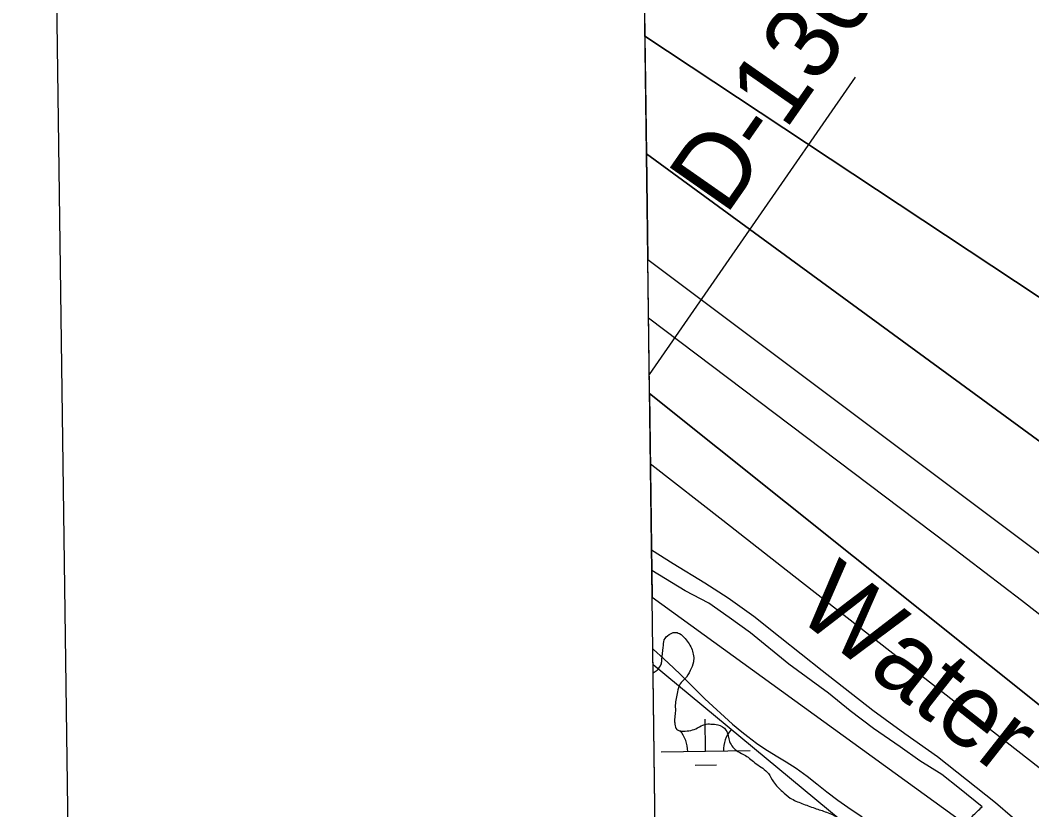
# Model space of a CAD drawing. Extents: x 3753511 to 3791668, y 379550 to 405377.
# Drawn here: x 3756853 to 3757989, y 399790 to 400676 of the extents above; entities that cross this region are included whole.
import ezdxf

# ---------------------------------------------------------------- set-up
doc = ezdxf.new("R2010")
doc.units = 0
for name, color, linetype in [('V-ANNO-SYMB', 7, 'Continuous'), ('V-GRID-FRAM', 7, 'Continuous'), ('V-RIVR-EDGE', 7, 'Continuous'), ('V-RIVR-IDEN', 7, 'Continuous'), ('V-RIVR-RANG', 7, 'Continuous'), ('V-RIVR-RANG-IDEN', 7, 'Continuous'), ('V-RRAP-FSHR', 7, 'Continuous'), ('V-TOPO-DPTH', 7, 'Continuous'), ('V-TOPO-MINR', 7, 'Continuous'), ('V-TOPO-WATR', 7, 'Continuous'), ('V-WETL-SWMP', 7, 'Continuous')]:
    doc.layers.add(name, color=color, linetype=linetype)

msp = doc.modelspace()

# ---------------------------------------------------------------- linework, layer by layer
at = {"layer": 'V-ANNO-SYMB'}
msp.add_lwpolyline([(3757162.5, 380795.6), (3790242.7, 381242.9), (3789932.8, 404157.4), (3756852.6, 403710.1), (3757162.5, 380795.6)], dxfattribs=at)
at = {"layer": 'V-GRID-FRAM'}
msp.add_lwpolyline([(3757521.7, 403151.1), (3789298.9, 403581), (3789552.8, 385400.3), (3757759.7, 384970.3), (3757521.7, 403151.1)], dxfattribs=at)
at = {"layer": 'V-RIVR-EDGE'}
for p, q in [((3757561.9, 400081.8), (3757586.1, 400066.5)), ((3757586.1, 400066.5), (3757621.6, 400044.9)), ((3757599.7, 400035.7), (3757562.2, 400058.7)), ((3757621.6, 400044.9), (3757647.8, 400027.9)), ((3757626, 400021.9), (3757599.7, 400035.7)), ((3757649, 400006.1), (3757626, 400021.9)), ((3757647.8, 400027.9), (3757676.5, 400007.6)), ((3757672.8, 399988.6), (3757649, 400006.1)), ((3757676.5, 400007.6), (3757706.4, 399983.7)), ((3757716, 399953.7), (3757672.8, 399988.6)), ((3757706.4, 399983.7), (3757753.6, 399946.4)), ((3757760.4, 399920.9), (3757716, 399953.7)), ((3757753.6, 399946.4), (3757810.5, 399902.1)), ((3757785, 399901), (3757760.4, 399920.9)), ((3757811.2, 399881.5), (3757785, 399901)), ((3757810.5, 399902.1), (3757824.2, 399892)), ((3757824.2, 399892), (3757846.4, 399875.8)), ((3757841.1, 399860.8), (3757811.2, 399881.5)), ((3757846.4, 399875.8), (3757883.1, 399849.8)), ((3757863.3, 399845), (3757841.1, 399860.8)), ((3757887.9, 399829.6), (3757863.3, 399845)), ((3757883.1, 399849.8), (3757948.1, 399798.3)), ((3757907.7, 399814.2), (3757887.9, 399829.6)), ((3757933.1, 399793.5), (3757907.7, 399814.2)), ((3757948.1, 399798.3), (3757986.4, 399765.4))]:
    msp.add_line(p, q, dxfattribs=at)
msp.add_spline([(3757563.7, 399944), (3757565.9, 399945.2), (3757570, 399949.2), (3757572.8, 399954.1), (3757573.3, 399958.9), (3757574.9, 399972.3), (3757576.1, 399980.8), (3757581.4, 399986.8), (3757587.9, 399989.2), (3757593.1, 399988), (3757599.6, 399982.3), (3757607.3, 399969.8), (3757608.8, 399956), (3757605.2, 399946.3), (3757599.1, 399937), (3757593.8, 399931.4), (3757591, 399922.5), (3757588.5, 399907.5), (3757588.5, 399899.1), (3757587.6, 399891.8), (3757588, 399886.1), (3757590, 399880.4), (3757593.3, 399878.8), (3757597.7, 399878.4), (3757613.5, 399882), (3757621.6, 399886), (3757628.5, 399886.4), (3757636.2, 399885.6), (3757645.4, 399879.5), (3757649.5, 399866.6), (3757658.7, 399855.6), (3757667.2, 399851.1), (3757679.3, 399841.8), (3757693, 399830.9), (3757698.7, 399821.5), (3757708.8, 399810.6), (3757717.6, 399803.3), (3757730.6, 399797.2), (3757745.1, 399791.9), (3757758.4, 399787.4), (3757772.6, 399780.5), (3757779.4, 399774.8), (3757786.3, 399763.9), (3757787.5, 399754.6), (3757790.3, 399741.7), (3757797.5, 399727.5), (3757806.8, 399714.1), (3757811.6, 399710.1), (3757818.9, 399710), (3757825, 399710.4), (3757839.1, 399716.9), (3757842.4, 399724.5), (3757849.7, 399748.4), (3757858.3, 399761.3), (3757870.4, 399768.6), (3757880.5, 399770.1), (3757899.5, 399770.5), (3757905.6, 399771.7), (3757922.2, 399783), (3757933.1, 399793.5)], degree=3, dxfattribs=at)
at = {"layer": 'V-RIVR-RANG'}
msp.add_line((3757559.3, 400278.6), (3757790.9, 400612.5), dxfattribs=at)
at = {"layer": 'V-RRAP-FSHR'}
msp.add_lwpolyline([(3757563.6, 399953.3), (3758068.9, 399534.7), (3758900.8, 398913.1), (3760489.6, 397842.2), (3761272.5, 397284.7), (3762001.9, 396825.7), (3763933.7, 395486.8), (3764514.9, 395076.7), (3765451.6, 394530.5), (3766076.4, 394191.3), (3766545.3, 393960.3), (3766679.9, 393930.1), (3766808.6, 393885.6), (3766901.8, 393826.8), (3766956.5, 393779.4), (3767086.7, 393701), (3767307.3, 393607.9), (3767495.3, 393505.5), (3767658.4, 393397.5), (3767773.5, 393285.8), (3767959.6, 393143.9), (3768482.9, 392725.4)], dxfattribs=at)
at = {"layer": 'V-TOPO-DPTH'}
for p, q in [((3757554.3, 400658.4), (3757556.1, 400526.3)), ((3757556.1, 400526.3), (3757557.6, 400407.9)), ((3757559.6, 400257.2), (3757557.6, 400407.9)), ((3757559.6, 400257.2), (3757562.6, 400028.8))]:
    msp.add_line(p, q, dxfattribs=at)
for points in [[(3757521.7, 403151.1), (3757554.3, 400658.4), (3758308.3, 400159.7), (3758311.3, 400157.8), (3758314.3, 400155.9), (3758317.4, 400154), (3758320.5, 400152.2), (3758446.1, 400079.5), (3758472.2, 400065.7), (3758498.8, 400053.3), (3758526.4, 400042.9), (3758554.5, 400033.8), (3758583.1, 400026.7), (3758612, 400020.7), (3758641.2, 400016.3), (3758670.6, 400013), (3758683.9, 400011.9), (3758719.7, 400007.4), (3758755.1, 400000.9), (3758789.8, 399991.4), (3758824, 399979.9), (3759244.8, 399818.4)], [(3759244.8, 399818.4), (3758824, 399979.9), (3758789.8, 399991.4), (3758755.1, 400000.9), (3758719.7, 400007.4), (3758683.9, 400011.9), (3758670.6, 400013), (3758641.2, 400016.3), (3758612, 400020.7), (3758583.1, 400026.7), (3758554.5, 400033.8), (3758526.4, 400042.9), (3758498.8, 400053.3), (3758472.2, 400065.7), (3758446.1, 400079.5), (3758320.5, 400152.2), (3758317.4, 400154), (3758314.3, 400155.9), (3758311.3, 400157.8), (3758308.3, 400159.7), (3757554.3, 400658.4)], [(3759035, 399447.3), (3759005.6, 399469.2), (3758976.2, 399491), (3758946.7, 399512.8), (3758917.2, 399534.5), (3758887.6, 399556.1), (3758858, 399577.7), (3758832.2, 399596.4), (3758789.6, 399627.3), (3758747, 399658.2), (3758704.4, 399689.1), (3758661.8, 399720), (3758543.7, 399805.6), (3758491.5, 399843.5), (3758439.4, 399881.3), (3758387.3, 399919.2), (3758335.2, 399957.1), (3758275.9, 400000.4), (3758253.5, 400016.7), (3758231.1, 400033.1), (3758208.8, 400049.4), (3758186.4, 400065.7), (3757556.1, 400526.3)], [(3757556.1, 400526.3), (3758186.4, 400065.7), (3758208.8, 400049.4), (3758231.1, 400033.1), (3758253.5, 400016.7), (3758275.9, 400000.4), (3758335.2, 399957.1), (3758387.3, 399919.2), (3758439.4, 399881.3), (3758491.5, 399843.5), (3758543.7, 399805.6), (3758661.8, 399720), (3758704.4, 399689.1), (3758747, 399658.2), (3758789.6, 399627.3), (3758832.2, 399596.4), (3758858, 399577.7), (3758887.6, 399556.1), (3758917.2, 399534.5), (3758946.7, 399512.8), (3758976.2, 399491), (3759005.6, 399469.2), (3759035, 399447.3)], [(3757557.6, 400407.9), (3758125.4, 399982.5), (3758149.2, 399964.7), (3758173, 399946.9), (3758196.8, 399929.2), (3758220.6, 399911.4), (3758267.2, 399876.8), (3758309.8, 399844.9), (3758352.2, 399812.8), (3758394.4, 399780.4)], [(3757557.6, 400407.9), (3758125.4, 399982.5), (3758149.2, 399964.7), (3758173, 399946.9), (3758196.8, 399929.2), (3758220.6, 399911.4), (3758267.2, 399876.8), (3758309.8, 399844.9), (3758352.2, 399812.8), (3758394.4, 399780.4)], [(3759483.3, 398745.3), (3758900.4, 399209), (3758704.3, 399361.8), (3758606.2, 399438.1), (3758507.9, 399514.1), (3758409.3, 399589.9), (3758310.6, 399665.4), (3758094.3, 399830.3), (3757559.6, 400257.2)], [(3759483.3, 398745.3), (3758900.4, 399209), (3758704.3, 399361.8), (3758606.2, 399438.1), (3758507.9, 399514.1), (3758409.3, 399589.9), (3758310.6, 399665.4), (3758094.3, 399830.3), (3757559.6, 400257.2)], [(3757562.6, 400028.8), (3757970, 399733.8)]]:
    msp.add_lwpolyline(points, dxfattribs=at)
at = {"layer": 'V-TOPO-MINR'}
for points in [[(3757554.3, 400658.4), (3758308.3, 400159.7), (3758311.3, 400157.8), (3758314.3, 400155.9), (3758317.4, 400154), (3758320.5, 400152.2), (3758446.1, 400079.5), (3758472.2, 400065.7), (3758498.8, 400053.3), (3758526.4, 400042.9), (3758554.5, 400033.8), (3758583.1, 400026.7), (3758612, 400020.7), (3758641.2, 400016.3), (3758670.6, 400013), (3758683.9, 400011.9), (3758719.7, 400007.4), (3758755.1, 400000.9), (3758789.8, 399991.4), (3758824, 399979.9), (3759244.8, 399818.4)], [(3757556.1, 400526.3), (3758186.4, 400065.7), (3758208.8, 400049.4), (3758231.1, 400033.1), (3758253.5, 400016.7), (3758275.9, 400000.4), (3758335.2, 399957.1), (3758387.3, 399919.2), (3758439.4, 399881.3), (3758491.5, 399843.5), (3758543.7, 399805.6), (3758661.8, 399720), (3758704.4, 399689.1), (3758747, 399658.2), (3758789.6, 399627.3), (3758832.2, 399596.4), (3758858, 399577.7), (3758887.6, 399556.1), (3758917.2, 399534.5), (3758946.7, 399512.8), (3758976.2, 399491), (3759005.6, 399469.2), (3759035, 399447.3)], [(3757557.6, 400407.9), (3758125.4, 399982.5), (3758149.2, 399964.7), (3758173, 399946.9), (3758196.8, 399929.2), (3758220.6, 399911.4), (3758267.2, 399876.8), (3758309.8, 399844.9), (3758352.2, 399812.8), (3758394.4, 399780.4)], [(3757558.5, 400342.3), (3757895, 400088.1), (3757936.2, 400056.8), (3757977.2, 400025.3), (3758018, 399993.6), (3758058.7, 399961.8), (3758076, 399948.1), (3758107.8, 399922.8), (3758139.5, 399897.3), (3758171, 399871.6), (3758202.4, 399845.7), (3758292.4, 399771)], [(3757559.6, 400257.2), (3758094.3, 399830.3), (3758310.6, 399665.4), (3758409.3, 399589.9), (3758507.9, 399514.1), (3758606.2, 399438.1), (3758704.3, 399361.8), (3758900.4, 399209), (3759483.3, 398745.3)], [(3757560.6, 400178.5), (3757562.1, 400177.3), (3757641.8, 400115), (3757721.6, 400052.6), (3758021.3, 399818.8), (3758042.6, 399802.2), (3758064, 399785.5)]]:
    msp.add_lwpolyline(points, dxfattribs=at)
at = {"layer": 'V-TOPO-WATR'}
msp.add_lwpolyline([(3757562.6, 400028.8), (3757970, 399733.8)], dxfattribs=at)
at = {"layer": 'V-WETL-SWMP'}
for p, q in [((3757568.7, 399560.9), (3757563.3, 399970.7)), ((3757563.3, 399970.7), (3757564.1, 399970)), ((3757564.1, 399970), (3757575.6, 399959.5)), ((3757575.6, 399959.5), (3757586.6, 399949.4)), ((3757586.6, 399949.4), (3757594.7, 399941.6)), ((3757594.7, 399941.6), (3757606.5, 399929.8)), ((3757606.5, 399929.8), (3757621.6, 399914.7)), ((3757621.6, 399914.7), (3757652.9, 399886.1)), ((3757622.5, 399855.8), (3757622, 399891.8)), ((3757652.9, 399886.1), (3757663.1, 399877.8)), ((3757663.1, 399877.8), (3757669.9, 399872.3)), ((3757669.9, 399872.3), (3757679.8, 399864.8)), ((3757679.8, 399864.8), (3757689.1, 399858.6)), ((3757572.5, 399855.1), (3757672.5, 399856.5)), ((3757689.1, 399858.6), (3757701.6, 399850.8)), ((3757701.6, 399850.8), (3757713, 399844.1)), ((3757610.7, 399840.2), (3757634.7, 399840.5)), ((3757713, 399844.1), (3757724.1, 399836.7)), ((3757724.1, 399836.7), (3757736.4, 399827.7)), ((3757736.4, 399827.7), (3757747.3, 399819.2)), ((3757747.3, 399819.2), (3757758.8, 399810.1)), ((3757758.8, 399810.1), (3757771, 399801.1)), ((3757771, 399801.1), (3757782.4, 399793.2)), ((3757782.4, 399793.2), (3757798.3, 399782.2))]:
    msp.add_line(p, q, dxfattribs=at)
for centre, start, end in [((3757567.3, 399855.5), 0.0029, 41.5465), ((3757677.8, 399857), 140.0029, 181.5465)]:
    msp.add_arc(centre, 35.2, start, end, dxfattribs=at)

# ---------------------------------------------------------------- texts
at = {"layer": 'V-RIVR-IDEN'}
msp.add_text('Water ', height=83, rotation=321.7956, dxfattribs=at).set_placement((3757720.8, 400009.2))
at = {"layer": 'V-RIVR-RANG-IDEN'}
msp.add_text('D-130', height=83, rotation=55.1083, dxfattribs=at).set_placement((3757645.2, 400456))

doc.saveas('drawing.dxf')
